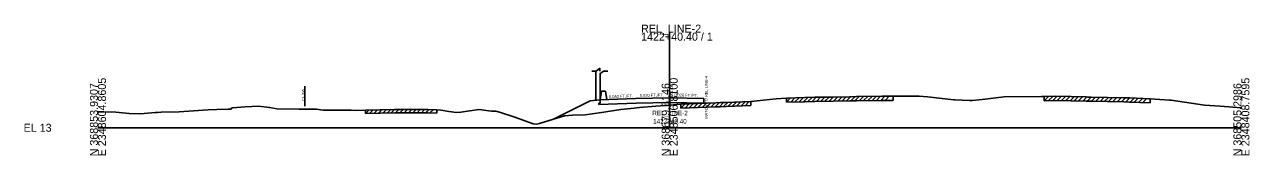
# Model space of a CAD drawing. Extents: x -26 to 2349775, y -10 to 368669.
# Drawn here: x -25.7 to 402.8, y -9.7 to 36.1 of the extents above; entities that cross this region are included whole.
import ezdxf

# ---------------------------------------------------------------- set-up
doc = ezdxf.new("R2010")
doc.units = 0
for name, color, linetype in [('Default', 7, 'Continuous'), ('RD_GPK_XS_Cell', 7, 'Continuous'), ('RD_PD_NOISE-WALL-GM', 7, 'Continuous'), ('RD_XS_Base', 7, 'Continuous'), ('RD_XS_EarthShd', 7, 'Continuous'), ('RD_XS_ExGround', 7, 'Continuous'), ('RD_XS_ExPaveRet', 7, 'Continuous'), ('RD_XS_ExRW', 7, 'Continuous'), ('RD_XS_MatchLine', 7, 'Continuous'), ('RD_XS_Pave', 7, 'Continuous'), ('RD_XS_PaveShd', 7, 'Continuous'), ('RD_XS_TieSlope', 7, 'Continuous'), ('RD_XS_TX_Elev_EX', 7, 'Continuous'), ('RD_XS_TX_Elev_PR', 7, 'Continuous'), ('RD_XS_TX_MatchLine', 7, 'Continuous'), ('RD_XS_TX_Slope', 7, 'Continuous'), ('RD_XS_TX_Station', 7, 'Continuous')]:
    doc.layers.add(name, color=color, linetype=linetype)

msp = doc.modelspace()

# ---------------------------------------------------------------- linework, layer by layer
at = {"layer": 'Default'}
for p, q in [((174.32, 19.83), (172.74, 19.83)), ((175.57, 20.86), (174.32, 19.83)), ((175.57, 19.83), (175.57, 20.86)), ((176.82, 19.83), (175.57, 18.81)), ((178.42, 19.83), (176.82, 19.83))]:
    msp.add_line(p, q, dxfattribs=at)
at = {"layer": 'RD_GPK_XS_Cell'}
for p, q in [((200, 0), (200, 33.23)), ((0, 0), (200, 0)), ((200, 0), (400, 0))]:
    msp.add_line(p, q, dxfattribs=at)
at = {"layer": 'RD_PD_NOISE-WALL-GM'}
for p, q in [((174.2, 19.83), (174.2, 9.61)), ((175.7, 9.73), (175.7, 18.91)), ((175.7, 9.82), (176.18, 12.82)), ((176.18, 12.82), (177.52, 12.82)), ((177.52, 12.82), (178, 9.82))]:
    msp.add_line(p, q, dxfattribs=at)
at = {"layer": 'RD_XS_Base'}
for p, q in [((175.7, 8.59), (175.2, 8.57)), ((188.24, 8.59), (175.2, 8.07)), ((175.7, 9.73), (175.7, 8.59)), ((200, 8.82), (188.24, 8.59)), ((200, 8.82), (212, 8.58)), ((175.2, 8.57), (175.2, 8.07))]:
    msp.add_line(p, q, dxfattribs=at)
at = {"layer": 'RD_XS_EarthShd'}
msp.add_line((175.7, 9.73), (172.24, 9.45), dxfattribs=at)
at = {"layer": 'RD_XS_ExGround'}
msp.add_lwpolyline([(0, 5.54), (0.62, 5.53), (6.29, 5.49), (10.93, 4.93), (14.91, 4.9), (20.05, 5.33), (20.85, 5.36), (22.14, 5.4), (28.36, 5.59), (30.03, 5.69), (38.55, 6.29), (41.63, 6.42), (45.53, 6.47), (46.14, 6.47), (46.54, 6.44), (46.69, 6.85), (47.04, 6.95), (51.52, 7.36), (56.12, 7.55), (60.07, 7.13), (62.53, 6.66), (70.38, 6.53), (72.42, 6.52), (73.17, 6.53), (76.44, 6.54), (78.84, 6.18), (88.62, 6.11), (89.98, 6.06), (93.63, 6.16), (103.9, 6.32), (105.75, 6.36), (115.38, 6.32), (118.6, 6.27), (120.09, 6.11), (122.78, 5.72), (125.46, 5.34), (126.9, 5.4), (133.3, 6.32), (137.67, 5.74), (139.21, 5.79), (140.48, 5.42), (145.83, 3.67), (152.25, 1.32), (153.47, 1.3), (154.43, 1.52), (157.86, 2.56), (163.21, 4.17), (166.04, 4.35), (170.4, 4.5), (177.01, 5.49), (178.32, 5.69), (182.18, 6.23), (182.96, 6.37), (187.63, 6.85), (188.39, 6.93), (189.43, 7.04), (195.22, 7.51), (200, 7.92), (202.64, 8.18), (203.88, 8.27), (216.1, 8.72), (217.82, 8.77), (219.76, 8.85), (228.42, 9.15), (237.29, 10.05), (240.83, 10.37), (247.33, 10.55), (250.8, 10.65), (257.21, 10.74), (263.03, 10.84), (265.33, 10.87), (274.31, 11), (275.1, 10.99), (278.22, 10.99), (281.22, 11.07), (287.28, 11.08), (290.25, 10.86), (299.43, 9.73), (299.79, 9.72), (304.88, 9.48), (305.99, 9.58), (310.37, 10.01), (314.12, 10.44), (316.98, 10.83), (330.08, 10.87), (331.05, 10.89), (335, 10.99), (345.72, 10.75), (346.13, 10.74), (347.45, 10.72), (358.88, 10.49), (360.86, 10.42), (368.04, 10.16), (374.82, 9.65), (375.48, 9.6), (377.78, 9.28), (387.06, 7.94), (392.6, 7.51), (400, 6.95)], dxfattribs=at)
at = {"layer": 'RD_XS_ExPaveRet'}
for p, q in [((211.38, 7.11), (212.87, 8.6)), ((212.88, 7.16), (214.37, 8.65)), ((214.38, 7.22), (215.87, 8.71)), ((215.88, 7.27), (217.37, 8.76)), ((217.38, 7.32), (218.88, 8.81)), ((218.88, 7.38), (220.38, 8.87)), ((220.38, 7.43), (221.87, 8.92)), ((221.88, 7.49), (223.37, 8.98)), ((223.38, 7.54), (224.87, 9.03)), ((224.88, 7.59), (226.37, 9.08)), ((226.38, 7.64), (227.87, 9.13)), ((228.42, 9.15), (228.42, 7.72)), ((240.83, 8.94), (242.31, 10.41)), ((240.83, 8.94), (240.83, 10.37)), ((240.83, 8.94), (247.33, 9.11)), ((242.33, 8.98), (243.81, 10.45)), ((243.83, 9.02), (245.31, 10.5)), ((245.33, 9.06), (246.81, 10.54)), ((246.83, 9.1), (248.31, 10.58)), ((247.33, 9.11), (250.8, 9.21)), ((248.33, 9.14), (249.81, 10.62)), ((249.83, 9.19), (251.3, 10.66)), ((250.8, 9.21), (257.21, 9.31)), ((251.33, 9.22), (252.79, 10.68)), ((252.83, 9.24), (254.29, 10.7)), ((254.33, 9.27), (255.79, 10.72)), ((255.83, 9.29), (257.29, 10.75)), ((257.21, 9.31), (263.03, 9.4)), ((257.33, 9.31), (258.79, 10.77)), ((258.83, 9.33), (260.29, 10.79)), ((260.33, 9.36), (261.79, 10.82)), ((261.83, 9.38), (263.29, 10.84)), ((263.03, 9.4), (265.33, 9.43)), ((263.33, 9.4), (264.79, 10.86)), ((264.83, 9.42), (266.29, 10.88)), ((265.33, 9.43), (274.31, 9.56)), ((266.33, 9.45), (267.79, 10.9)), ((267.83, 9.47), (269.29, 10.92)), ((269.33, 9.49), (270.79, 10.95)), ((270.83, 9.51), (272.29, 10.97)), ((272.33, 9.53), (273.79, 10.99)), ((273.83, 9.55), (275.27, 10.99)), ((274.31, 9.56), (275.1, 9.56)), ((275.1, 9.56), (278.22, 9.55)), ((275.33, 9.56), (276.76, 10.99)), ((278.22, 10.99), (278.22, 9.55)), ((331.05, 9.45), (332.52, 10.93)), ((331.05, 9.45), (331.05, 10.89)), ((331.05, 9.45), (335, 9.55)), ((332.55, 9.49), (334.02, 10.97)), ((334.05, 9.53), (335.5, 10.98)), ((335, 9.55), (345.72, 9.31)), ((335.55, 9.54), (336.96, 10.95)), ((337.05, 9.51), (338.46, 10.91)), ((338.55, 9.47), (339.96, 10.88)), ((340.05, 9.44), (341.46, 10.85)), ((341.55, 9.41), (342.96, 10.81)), ((343.05, 9.37), (344.46, 10.78)), ((344.55, 9.34), (345.96, 10.75)), ((345.72, 9.31), (346.13, 9.31)), ((346.05, 9.31), (347.46, 10.72)), ((346.13, 9.31), (347.45, 9.28)), ((347.45, 9.28), (358.88, 9.05)), ((347.55, 9.28), (348.96, 10.69)), ((349.05, 9.25), (350.46, 10.66)), ((350.55, 9.22), (351.96, 10.63)), ((352.05, 9.19), (353.46, 10.6)), ((353.55, 9.16), (354.96, 10.57)), ((355.05, 9.13), (356.46, 10.54)), ((356.55, 9.1), (357.96, 10.51)), ((358.05, 9.07), (359.45, 10.47)), ((358.88, 9.05), (360.86, 8.98)), ((359.55, 9.03), (360.94, 10.42)), ((360.86, 8.98), (368.04, 8.73)), ((361.05, 8.97), (362.44, 10.36)), ((362.55, 8.92), (363.94, 10.31)), ((364.05, 8.87), (365.44, 10.26)), ((365.55, 8.81), (366.94, 10.2)), ((368.04, 10.16), (368.04, 8.73)), ((93.63, 5.02), (94.79, 6.18)), ((93.63, 5.02), (93.63, 6.16)), ((93.63, 5.02), (103.9, 5.18)), ((95.13, 5.05), (96.29, 6.21)), ((96.63, 5.07), (97.79, 6.23)), ((98.13, 5.09), (99.29, 6.25)), ((99.63, 5.12), (100.79, 6.28)), ((101.13, 5.14), (102.29, 6.3)), ((102.63, 5.16), (103.79, 6.32)), ((103.9, 5.18), (105.75, 5.22)), ((104.13, 5.19), (105.3, 6.35)), ((105.63, 5.22), (106.77, 6.36)), ((105.75, 5.22), (115.38, 5.18)), ((107.13, 5.21), (108.27, 6.35)), ((108.63, 5.21), (109.77, 6.35)), ((110.13, 5.2), (111.27, 6.34)), ((111.63, 5.19), (112.77, 6.33)), ((113.13, 5.19), (114.27, 6.32)), ((114.63, 5.18), (115.77, 6.31)), ((115.38, 5.18), (118.6, 5.13)), ((116.13, 5.16), (117.26, 6.29)), ((118.6, 6.27), (118.6, 5.13)), ((203.88, 6.83), (205.37, 8.32)), ((203.88, 6.83), (203.88, 8.27)), ((203.88, 6.83), (216.1, 7.28)), ((205.38, 6.89), (206.87, 8.38)), ((206.88, 6.94), (208.37, 8.43)), ((208.38, 7), (209.87, 8.49)), ((209.88, 7.05), (211.37, 8.54)), ((216.1, 7.28), (217.82, 7.34)), ((217.82, 7.34), (219.76, 7.41)), ((219.76, 7.41), (228.42, 7.72))]:
    msp.add_line(p, q, dxfattribs=at)
at = {"layer": 'RD_XS_ExRW'}
msp.add_line((72.38, 7.52), (72.38, 14.52), dxfattribs=at)
at = {"layer": 'RD_XS_MatchLine'}
msp.add_line((212, 10.22), (212, 8.57), dxfattribs=at)
at = {"layer": 'RD_XS_Pave'}
for q in [(188, 10.22), (212, 10.22)]:
    msp.add_line((200, 10.46), q, dxfattribs=at)
at = {"layer": 'RD_XS_PaveShd'}
msp.add_line((188, 10.22), (175.7, 9.73), dxfattribs=at)
at = {"layer": 'RD_XS_TieSlope'}
msp.add_line((172.24, 9.45), (159.37, 3.02), dxfattribs=at)

# ---------------------------------------------------------------- texts
at = {"layer": 'RD_GPK_XS_Cell'}
for s, p in [('REL_LINE-2', (190, 33.23)), ('1422+40.40 / 1', (190, 30.43)), ('EL 13', (-26, -1.4))]:
    msp.add_text(s, height=2.8, dxfattribs=at).set_placement(p)
for s, p in [('E 2348604.8605', (2.8, -10)), ('E 2348506.8100', (202.8, -10)), ('E 2348408.7595', (402.8, -10)), ('N 368853.9307', (0, -10)), ('N 368679.6146', (200, -10)), ('N 368505.2986', (400, -10))]:
    msp.add_text(s, height=2.8, rotation=90, dxfattribs=at).set_placement(p)
at = {"layer": 'RD_XS_ExRW'}
msp.add_text('EX. R/W ', height=0.75, rotation=90, dxfattribs=at).set_placement((72.13, 9.48))
at = {"layer": 'RD_XS_TX_Elev_EX'}
msp.add_text('20.92', height=1, rotation=90, dxfattribs=at).set_placement((200.5, 7.92))
at = {"layer": 'RD_XS_TX_Elev_PR'}
msp.add_text(' 23.46', height=1.2, rotation=90, dxfattribs=at).set_placement((201.2, 10.46))
at = {"layer": 'RD_XS_TX_MatchLine'}
msp.add_text('MATCH TO REL LINE-4', height=1, rotation=90, dxfattribs=at).set_placement((213.31, 3.14))
at = {"layer": 'RD_XS_TX_Slope'}
for s, rotation, p in [('0.040 FT./FT.', 2.2906, (178.79, 10.33)), ('0.020 FT./FT.', 1.1458, (189.58, 10.78)), ('0.020 FT./FT.', 358.8542, (201.6, 10.94))]:
    msp.add_text(s, height=1, rotation=rotation, dxfattribs=at).set_placement(p)
at = {"layer": 'RD_XS_TX_Station'}
for s, p in [('REL_LINE-2', (193.93, 4.36)), ('1422+40.40', (194.23, 1.46))]:
    msp.add_text(s, height=1.6, dxfattribs=at).set_placement(p)

doc.saveas('drawing.dxf')
